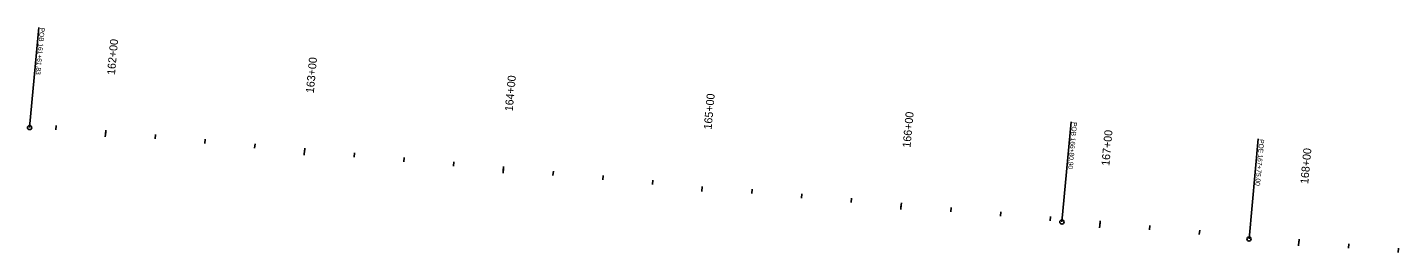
# Model space of a CAD drawing. Extents: x 20499876 to 20505320, y 7953544 to 7954108.
# Drawn here: x 20499876 to 20500563, y 7953995 to 7954108 of the extents above; entities that cross this region are included whole.
import ezdxf

# ---------------------------------------------------------------- set-up
doc = ezdxf.new("R2010")
doc.units = 0
for name, color, linetype in [('Curb', 7, 'Continuous'), ('Draft_7', 7, 'Continuous'), ('Text', 7, 'Continuous')]:
    doc.layers.add(name, color=color, linetype=linetype)

msp = doc.modelspace()

# ---------------------------------------------------------------- linework, layer by layer
at = {"layer": 'Curb'}
for p, q in [((20499915.49, 7954054.48), (20499915.68, 7954056.65)), ((20500015.07, 7954045.36), (20500015.27, 7954047.54)), ((20500114.65, 7954036.25), (20500114.85, 7954038.43)), ((20500214.35, 7954028.36), (20500214.13, 7954025.92)), ((20500313.82, 7954018.02), (20500314.02, 7954020.2)), ((20500413.4, 7954008.91), (20500413.6, 7954011.09)), ((20500413.4, 7954008.91), (20500413.6, 7954011.09)), ((20500512.99, 7953999.8), (20500513.19, 7954001.97))]:
    msp.add_line(p, q, dxfattribs=at)
at = {"layer": 'Draft_7'}
for p, q in [((20499890.59, 7954056.75), (20499890.79, 7954058.93)), ((20499915.6, 7954055.7), (20499915.37, 7954053.26)), ((20499940.38, 7954052.2), (20499940.58, 7954054.37)), ((20499965.28, 7954049.92), (20499965.48, 7954052.09)), ((20499990.17, 7954047.64), (20499990.37, 7954049.82)), ((20500015.18, 7954046.58), (20500014.96, 7954044.14)), ((20500039.97, 7954043.09), (20500040.16, 7954045.26)), ((20500064.86, 7954040.81), (20500065.06, 7954042.98)), ((20500089.76, 7954038.53), (20500089.96, 7954040.7)), ((20500114.76, 7954037.47), (20500114.54, 7954035.03)), ((20500139.55, 7954033.97), (20500139.75, 7954036.15)), ((20500164.45, 7954031.69), (20500164.64, 7954033.87)), ((20500189.34, 7954029.42), (20500189.54, 7954031.59)), ((20500214.35, 7954028.36), (20500214.13, 7954025.92)), ((20500239.13, 7954024.86), (20500239.33, 7954027.03)), ((20500264.03, 7954022.58), (20500264.23, 7954024.76)), ((20500288.93, 7954020.3), (20500289.12, 7954022.48)), ((20500313.93, 7954019.24), (20500313.71, 7954016.81)), ((20500338.72, 7954015.75), (20500338.92, 7954017.92)), ((20500363.61, 7954013.47), (20500363.81, 7954015.64)), ((20500388.51, 7954011.19), (20500388.71, 7954013.36)), ((20500413.52, 7954010.13), (20500413.29, 7954007.69)), ((20500413.52, 7954010.13), (20500413.29, 7954007.69)), ((20500438.3, 7954006.63), (20500438.5, 7954008.81)), ((20500438.3, 7954006.63), (20500438.5, 7954008.81)), ((20500463.2, 7954004.36), (20500463.39, 7954006.53)), ((20500463.2, 7954004.36), (20500463.4, 7954006.53)), ((20500488.09, 7954002.08), (20500488.29, 7954004.25)), ((20500513.1, 7954001.02), (20500512.88, 7953998.58)), ((20500537.88, 7953997.52), (20500538.08, 7953999.7)), ((20500562.78, 7953995.24), (20500562.98, 7953997.42))]:
    msp.add_line(p, q, dxfattribs=at)
at = {"layer": 'Text'}
for p, q in [((20499877.47, 7954057.95), (20499882.07, 7954108.14)), ((20499882.07, 7954108.14), (20499882.07, 7954108.14)), ((20500394.39, 7954010.65), (20500398.98, 7954060.84)), ((20500398.98, 7954060.84), (20500398.98, 7954060.84)), ((20500488.09, 7954002.08), (20500492.68, 7954052.27)), ((20500492.68, 7954052.27), (20500492.68, 7954052.27))]:
    msp.add_line(p, q, dxfattribs=at)
for centre in [(20499877.47, 7954057.95), (20500394.39, 7954010.65), (20500488.09, 7954002.08)]:
    msp.add_circle(centre, 1.07, dxfattribs=at)

# ---------------------------------------------------------------- texts
at = {"layer": 'Curb'}
msp.add_text('165+00', height=4.008, rotation=84.77145, dxfattribs=at).set_placement((20500218.97, 7954056.83))
at = {"layer": 'Draft_7'}
for s, p in [('162+00', (20499920.21, 7954084.17)), ('163+00', (20500019.8, 7954075.06)), ('164+00', (20500119.38, 7954065.94)), ('165+00', (20500218.97, 7954056.83)), ('166+00', (20500318.55, 7954047.72)), ('167+00', (20500418.13, 7954038.6)), ('167+00', (20500418.13, 7954038.6)), ('168+00', (20500517.72, 7954029.49))]:
    msp.add_text(s, height=4.008, rotation=84.77145, dxfattribs=at).set_placement(p)
at = {"layer": 'Text'}
for s, p in [('POB ', (20499882.71, 7954108.09)), ('161+61.83', (20499881.99, 7954100.23)), ('POB ', (20500399.62, 7954060.78)), ('166+80.90', (20500398.9, 7954052.93)), ('POE ', (20500493.33, 7954052.21)), ('167+75.00', (20500492.63, 7954044.54))]:
    msp.add_text(s, height=2.4, rotation=264.77145, dxfattribs=at).set_placement(p)

doc.saveas('drawing.dxf')
